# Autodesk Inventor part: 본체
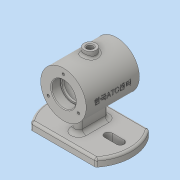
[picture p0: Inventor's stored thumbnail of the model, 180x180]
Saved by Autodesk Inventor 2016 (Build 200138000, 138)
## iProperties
Created: 2017-12
Part Number: 본체
Material: 일반
Document SubType Name: Modeling
Designer: 605-15
Density: 1 g/cm^3
Appearance: 기본값
Mass: 172.58 g
Surface Area: 486.488 cm^2
Volume: 172.58 cm^3
Author: 605-15
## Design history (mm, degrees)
sketch "스케치1"
  geometry: L1 (42.426, 35)-(-42.426, 35); L2 (42.426, -35)-(-42.426, -35); A1 r 55 centre (0, 0) between (-42.426, 35) and (-42.426, -35); A2 r 55 centre (0, 0) between (42.426, -35) and (42.426, 35); 1 further point
  constraints: 4 end point, 4 point on circle, 2 centre point, 2 horizontal, 1 coincident
  dimensions: "d1" = 70 distance between parallel lines of L2 L1; "d2" = 35 distance from line of point (0, 0) L1
extrude "돌출1" new body sketch "스케치1" distance "d3" = 10; taper "d4" = 0 deg
sketch "스케치2"
  geometry: L1 (0, 0)-(0, 62); C1 r 30 at (0, 62)
  constraints: 2 end point, 1 centre point, 1 coincident, 1 vertical
  dimensions: "d5" = 62 distance of L1.start L1.end; "d6" = 60 diameter of C1
extrude "돌출2" join sketch "스케치2" distance "d7" = 35; taper "d9" = 0 deg; dims "d8" = 35, "d10" = 0
sketch "스케치3"
  geometry: L1 (0, 15)-(0, -15); L2 (5, 15)-(5, -15); L3 (-5, -15)-(-5, 15); A1 r 5 centre (0, 15) between (5, 15) and (-5, 15); A2 r 5 centre (0, -15) between (-5, -15) and (5, -15); 1 further point
  constraints: 8 end point, 4 point on circle, 4 tangent, 2 centre point, 1 midpoint, 1 parallel, 1 vertical
  dimensions: "d11" = 5 radius of A2; "d12" = 30 distance of L1.start L1.end
extrude "돌출3" join sketch "스케치3" stored distance "d13" = 35; taper "d14" = 0 deg
node "작업 평면1"
sketch "스케치5"
  geometry: C1 r 8 at (0, 0); 1 further point
  constraints: 1 centre point, 1 coincident
  dimensions: "d24" = 16 diameter of C1
extrude "돌출4" join sketch "스케치5" distance "d25" = 37; taper "d26" = 0 deg
sketch "스케치4"
  geometry: L1 (62, 35)-(62, -35); L2 (32, -35)-(92, -35) reference; L3 (0, -35)-(0, 35) reference; L4 (92, 35)-(32, 35) reference; L5 (62, 35)-(78, 35); L6 (78, 35)-(78, 23); L7 (78, 23)-(76, 23); L8 (76, 23)-(76, 20); L9 (76, 20)-(87, 20); L10 (87, 20)-(87, -20); L11 (87, -20)-(76, -20); L12 (76, -20)-(76, -23); L13 (76, -23)-(78, -23); L14 (78, -23)-(78, -35); L15 (78, -35)-(62, -35); 1 further point
  constraints: 24 end point, 6 perpendicular, 6 point on line, 2 midpoint, 2 vertical, 1 collinear
  dimensions: "d15" = 62 distance between parallel lines of L3 L1; "d16" = 16 distance between parallel lines of L1 L6; "d17" = 14 distance between parallel lines of L1 L8; "d18" = 25 distance between parallel lines of L1 L10; "d19" = 12 distance of L5.end L6.end; "d20" = 40 distance of L9.end L10.end; "d21" = 12 distance of L13.end L14.end; "d22" = 3 distance of L7.end L8.end
revolve "회전1" sketch "스케치4" stored, may be unused: angle "d27" = 90 deg
fillet "모깎기1" dims "d28" = 3
fillet "모깎기2" dims "d29" = 0.3
chamfer "모따기1" distance "d30" = 1; stored, may be unused: second distance "d31" = 2, angle "d32" = 45 deg
sketch "스케치6"
  geometry: C1 r 4 at (0, 0); 1 further point
  constraints: 1 centre point, 1 coincident
  dimensions: "d33" = 8 diameter of C1
extrude "돌출5" cut sketch "스케치6" stored distance "d34" = 37; taper "d35" = 0 deg
chamfer "모따기2" distance "d36" = 1; stored, may be unused: second distance "d37" = 2, angle "d38" = 45 deg
sketch "스케치7"
  geometry: L1 (-24, 0)-(-40, 0); L2 (-24, -5)-(-40, -5); L3 (-40, 5)-(-24, 5); L4 (0, 0)-(-79.704, 0); L5 (0, 0)-(0, 84.273); L6 (40, 5)-(24, 5); L7 (24, -5)-(40, -5); C1 r 5 at (0, 0) reference; A1 r 5 centre (-24, 0) between (-24, -5) and (-24, 5); A2 r 5 centre (-40, 0) between (-40, 5) and (-40, -5); A3 r 5 centre (40, 0) between (40, -5) and (40, 5); A4 r 5 centre (24, 0) between (24, 5) and (24, -5); 1 further point
  constraints: 16 end point, 8 point on circle, 6 symmetric about line, 4 centre point, 4 tangent, 2 horizontal, 1 midpoint, 1 parallel, 1 point on line, 1 vertical, 2 other
  dimensions: "d39" = 16 distance of L1.start L1.end; "d40" = 5 radius of A2; "d63" = 24 distance from line of L1.start L5
extrude "돌출6" cut sketch "스케치7" stored distance "d43" = 37; taper "d44" = 0 deg
sketch "스케치8"
  geometry: L1 (0, 0)-(0, 23); 1 further point
  constraints: 2 end point, 1 vertical
  dimensions: "d45" = 23 distance of L1.start L1.end
hole "구멍1" sketch "스케치8" at (0, 23) diameter "d46" = 3.242; stored, may be unused: countersink angle "d50" = 90 deg, drill point angle "d52" = 118 deg; dims "d47" = 8, "d48" = 4, "d49" = 2, "d51" = 10
fillet "모깎기3" dims "d56" = 5
fillet "모깎기4" dims "d57" = 3
node "작업 평면2"
sketch "스케치9"
  geometry: L1 (30, 35)-(-30, 35) reference; L2 (30, -35)-(30, 35) reference; 2 further points
  constraints: 1 other
  dimensions: "d58" = 35 distance from line of point (0, 0) L1; "d59" = 30 distance from line of L2 point (0, 0)
feature "엠보싱1" sketch "스케치9" dims "d1" = 70, "d2" = 35, "d60" = 0.5, "d61" = 0
node "솔리드1"
pattern_circular "원형 패턴1" dims angle "d54" = 360 deg
mirror "대칭1"
other parameters: "d23" = 62
